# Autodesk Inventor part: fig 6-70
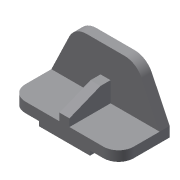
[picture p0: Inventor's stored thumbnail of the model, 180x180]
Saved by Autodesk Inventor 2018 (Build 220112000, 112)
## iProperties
Shininess: 77.0
Length Units: 11269
Angle Units: 11279
Time Units: 11290
Mass Units: 11283
Length Display Precision: 3
Angle Display Precision: 2
Created: 2001-12
Part Number: fig 6-70
Document SubType Name: Modeling
Designer: Renu Muthoo
Density: 1 g/cm^3
Material: Generic
Appearance: Default
Density: 0.0
Volumn: 0.0
Area: 0.0
PropertySet Name: Model Information
Control State: 0
Master: False
Checked Out: False
Author: Renu Muthoo
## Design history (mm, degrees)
sketch "Sketch2"
  geometry: L1 (-67.219, 19.116)-(148.781, 19.116); L2 (148.781, 19.116)-(148.781, -0.884); L3 (-67.219, -0.884)-(-67.219, 19.116); L4 (-10.219, -0.884)-(-10.219, -9.884); L5 (-10.219, -9.884)-(91.781, -9.884); L6 (91.781, -9.884)-(91.781, -0.884); L7 (148.781, -0.884)-(91.781, -0.884); L8 (-10.219, -0.884)-(-67.219, -0.884)
  constraints: 16 end point, 5 parallel, 4 perpendicular, 2 equal length, 1 horizontal
  dimensions: "d0" = 102 distance of L4.end L5.end; "d1" = 57 distance of L4.start L3.start; "d2" = 29 distance between parallel lines of L1 L5; "d3" = 20 distance of L1.end L2.end
extrude "Extrusion1" new body sketch "Sketch2" distance "d4" = 102; taper "d5" = 0 deg
sketch "Sketch3"
  geometry: L1 (67.219, -19.116)-(-148.781, -19.116) reference; L2 (67.219, -19.116)-(31.475, -93.564); L3 (-2.781, -115.116)-(-78.781, -115.116); L4 (-113.038, -93.564)-(-148.781, -19.116); A1 r 38 centre (-2.781, -77.116) between (-2.781, -115.116) and (31.475, -93.564); A2 r 38 centre (-78.781, -77.116) between (-113.038, -93.564) and (-78.781, -115.116)
  constraints: 6 end point, 4 point on circle, 4 tangent, 2 centre point, 1 equal length, 1 equal radius, 1 parallel
  dimensions: "d6" = 96 distance between parallel lines of L3 L1; "d7" = 38 radius of A1; "d8" = 76 distance of A2.centre A1.centre
extrude "Extrusion2" join sketch "Sketch3" distance "d9" = 20; taper "d10" = 0 deg
fillet "Fillet1" dims "d11" = 30
workplane "Work Plane1"
sketch "Sketch7"
  geometry: L1 (0, -82)-(-15, -82); L2 (-15, -82)-(-40, -20); L3 (-40, -20)-(-40, 0); L4 (0, -82)-(20, -82) reference; L5 (0, 0)-(-74.447, 0) reference
  constraints: 6 end point, 2 point on line, 1 horizontal, 1 perpendicular
  dimensions: "d32" = 20 distance of L2.end L3.end; "d33" = 15 distance of L1.start L1.end; "d34" = 40 distance of L5.start L3.end
feature "Rib4" sketch "Sketch7" dims "d55" = 1, "d56" = 20, "d57" = 0
body "Solid1"
other parameters: "d12" = -108
